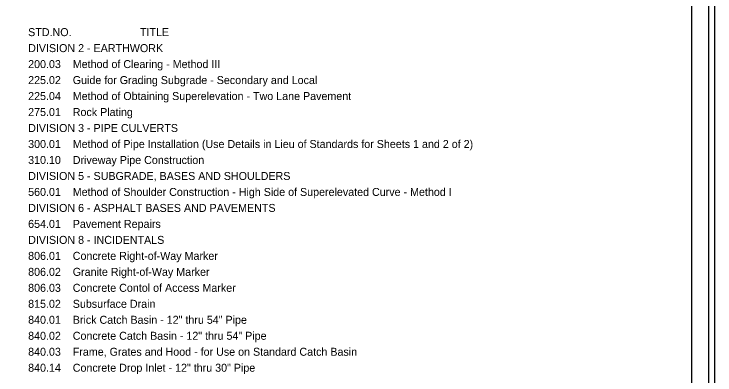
# Model space of a CAD drawing. Extents: x 3312684 to 3314684, y -677777 to -676682.
# Drawn here: x 3314171 to 3314684, y -677225 to -676961 of the extents above; entities that cross this region are included whole.
import ezdxf

# ---------------------------------------------------------------- set-up
doc = ezdxf.new("R2010")
doc.units = 0
for name, color, linetype in [('Default', 7, 'Continuous'), ('Sheet Plan CELL', 7, 'Continuous'), ('Sheet Plot Border Inside CELL', 7, 'Continuous'), ('Sheet Plot Border Outside CELL', 7, 'Continuous')]:
    doc.layers.add(name, color=color, linetype=linetype)

msp = doc.modelspace()

# ---------------------------------------------------------------- linework, layer by layer
at = {"layer": 'Sheet Plan CELL'}
msp.add_lwpolyline([(3314666.73, -676704.55), (3313166.73, -676704.55), (3313166.73, -677754.55), (3314666.73, -677754.55)], close=True, dxfattribs=at)
at = {"layer": 'Sheet Plot Border Inside CELL'}
msp.add_lwpolyline([(3313013.23, -677757.05), (3314679.23, -677757.05), (3314679.23, -676702.05), (3313013.23, -676702.05)], close=True, dxfattribs=at)
at = {"layer": 'Sheet Plot Border Outside CELL'}
msp.add_lwpolyline([(3313000.23, -677777.05), (3314683.73, -677777.05), (3314683.73, -676682.05), (3313000.23, -676682.05)], close=True, dxfattribs=at)

# ---------------------------------------------------------------- texts
at = {"layer": 'Default'}
for s, p in [('STD.NO.                       TITLE', (3314181.69, -676977.04)), ('DIVISION 2 - EARTHWORK', (3314181.69, -676988.74)), ('200.03    Method of Clearing - Method III', (3314181.69, -677000.44)), ('225.02    Guide for Grading Subgrade - Secondary and Local', (3314181.69, -677012.14)), ('225.04    Method of Obtaining Superelevation - Two Lane Pavement', (3314181.69, -677023.84)), ('275.01    Rock Plating ', (3314181.69, -677035.54)), ('DIVISION 3 - PIPE CULVERTS', (3314181.69, -677047.24)), ('300.01    Method of Pipe Installation (Use Details in Lieu of Standards for Sheets 1 and 2 of 2)', (3314181.69, -677058.94)), ('310.10    Driveway Pipe Construction', (3314181.69, -677070.64)), ('DIVISION 5 - SUBGRADE, BASES AND SHOULDERS', (3314181.69, -677082.34)), ('560.01    Method of Shoulder Construction - High Side of Superelevated Curve - Method I', (3314181.69, -677094.04)), ('DIVISION 6 - ASPHALT BASES AND PAVEMENTS', (3314181.69, -677105.74)), ('654.01    Pavement Repairs', (3314181.69, -677117.44)), ('DIVISION 8 - INCIDENTALS', (3314181.69, -677129.14)), ('806.01    Concrete Right-of-Way Marker', (3314181.69, -677140.84)), ('806.02    Granite Right-of-Way Marker', (3314181.69, -677152.54)), ('806.03    Concrete Contol of Access Marker', (3314181.69, -677164.24)), ('815.02    Subsurface Drain', (3314181.69, -677175.94)), ('840.01    Brick Catch Basin - 12" thru 54" Pipe', (3314181.69, -677187.64)), ('840.02    Concrete Catch Basin - 12" thru 54" Pipe', (3314181.69, -677199.34)), ('840.03    Frame, Grates and Hood - for Use on Standard Catch Basin', (3314181.69, -677211.04)), ('840.14    Concrete Drop Inlet - 12" thru 30" Pipe', (3314181.69, -677222.74))]:
    msp.add_text(s, height=5.85, dxfattribs=at).set_placement(p)

doc.saveas('drawing.dxf')
